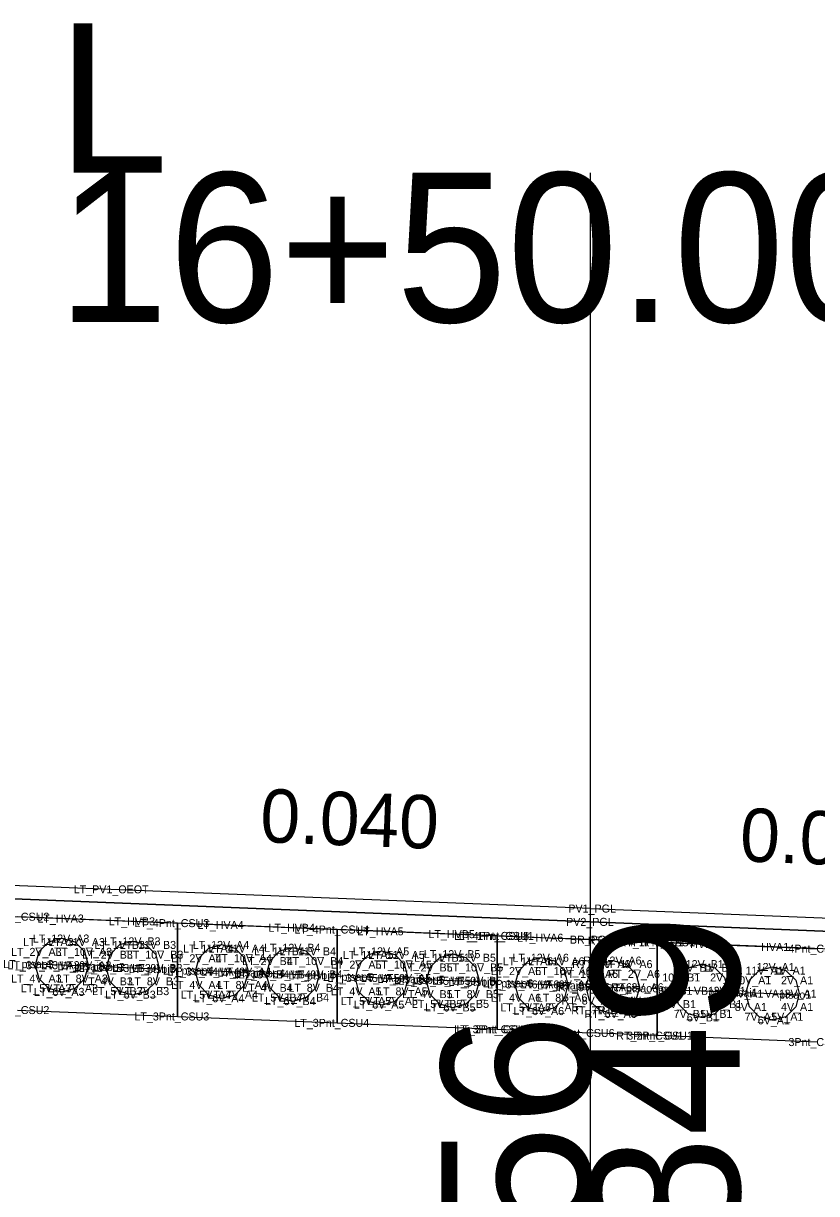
# Model space of a CAD drawing. Extents: x -26 to 1163, y -10 to 9537.
# Drawn here: x 69.36 to 84.24, y 6512.25 to 6534.18 of the extents above; entities that cross this region are included whole.
import ezdxf

# ---------------------------------------------------------------- set-up
doc = ezdxf.new("R2010")
doc.units = 0
for name, color, linetype in [('Exist Cross Section Cell', 7, 'Continuous'), ('Prop CMT Concrete Structures', 7, 'Continuous'), ('Prop CMT Corridor Surface Symbology Blue', 7, 'Continuous'), ('Prop CMT Pvmt Course 1', 7, 'Continuous'), ('Prop CMT Pvmt Course 2', 7, 'Continuous'), ('Prop XS SE Text', 7, 'Continuous'), ('Scratch_Level_0', 7, 'Continuous')]:
    doc.layers.add(name, color=color, linetype=linetype)

msp = doc.modelspace()

# ---------------------------------------------------------------- linework, layer by layer
at = {"layer": 'Exist Cross Section Cell'}
msp.add_line((80, 6500), (80, 6531.385), dxfattribs=at)
at = {"layer": 'Prop CMT Concrete Structures'}
for points in [[(72.25, 6517.317), (71.417, 6517.35), (70.083, 6517.403), (69.25, 6517.437)], [(75.25, 6517.197), (74.417, 6517.23), (73.083, 6517.283), (72.25, 6517.317)], [(72.25, 6517.317), (72.25, 6515.567)], [(72.25, 6515.567), (72.25, 6517.317)], [(78.25, 6517.077), (77.417, 6517.11), (76.083, 6517.163), (75.25, 6517.197)], [(75.25, 6517.197), (75.25, 6515.447)], [(75.25, 6515.447), (75.25, 6517.197)], [(70.083, 6517.028), (69.833, 6516.961), (69.65, 6516.778), (69.583, 6516.528)], [(70.583, 6516.528), (70.516, 6516.778), (70.333, 6516.961), (70.083, 6517.028)], [(71.417, 6516.975), (71.167, 6516.908), (70.984, 6516.725), (70.917, 6516.475)], [(71.917, 6516.475), (71.85, 6516.725), (71.667, 6516.908), (71.417, 6516.975)], [(80, 6517.007), (79.083, 6517.043), (78.25, 6517.077)], [(78.25, 6517.077), (78.25, 6515.327)], [(78.25, 6515.327), (78.25, 6517.077)], [(80, 6515.257), (80, 6517.007)], [(80, 6517.007), (80.417, 6516.99), (81.25, 6516.957)], [(80, 6515.257), (80, 6517.007)], [(81.25, 6516.957), (81.25, 6515.207)], [(81.25, 6516.957), (82.083, 6516.923), (83.417, 6516.87), (84.25, 6516.837)], [(81.25, 6515.207), (81.25, 6516.957)], [(73.083, 6516.908), (72.833, 6516.841), (72.65, 6516.658), (72.583, 6516.408)], [(73.583, 6516.408), (73.516, 6516.658), (73.333, 6516.841), (73.083, 6516.908)], [(74.417, 6516.855), (74.167, 6516.788), (73.984, 6516.605), (73.917, 6516.355)], [(74.917, 6516.355), (74.85, 6516.605), (74.667, 6516.788), (74.417, 6516.855)], [(76.083, 6516.788), (75.833, 6516.721), (75.65, 6516.538), (75.583, 6516.288)], [(76.583, 6516.288), (76.516, 6516.538), (76.333, 6516.721), (76.083, 6516.788)], [(77.417, 6516.735), (77.167, 6516.668), (76.984, 6516.485), (76.917, 6516.235)], [(77.917, 6516.235), (77.85, 6516.485), (77.667, 6516.668), (77.417, 6516.735)], [(69.583, 6516.528), (69.65, 6516.278), (69.833, 6516.095), (70.083, 6516.028), (70.333, 6516.095), (70.516, 6516.278), (70.583, 6516.528)], [(79.083, 6516.668), (78.833, 6516.601), (78.65, 6516.418), (78.583, 6516.168)], [(79.583, 6516.168), (79.516, 6516.418), (79.333, 6516.601), (79.083, 6516.668)], [(79.917, 6516.115), (79.984, 6516.365), (80.167, 6516.548), (80.417, 6516.615)], [(80.417, 6516.615), (80.667, 6516.548), (80.85, 6516.365), (80.917, 6516.115)], [(81.583, 6516.048), (81.65, 6516.298), (81.833, 6516.481), (82.083, 6516.548)], [(82.083, 6516.548), (82.333, 6516.481), (82.516, 6516.298), (82.583, 6516.048)], [(70.917, 6516.475), (70.984, 6516.225), (71.167, 6516.042), (71.417, 6515.975), (71.667, 6516.042), (71.85, 6516.225), (71.917, 6516.475)], [(72.583, 6516.408), (72.65, 6516.158), (72.833, 6515.975), (73.083, 6515.908), (73.333, 6515.975), (73.516, 6516.158), (73.583, 6516.408)], [(73.917, 6516.355), (73.984, 6516.105), (74.167, 6515.922), (74.417, 6515.855), (74.667, 6515.922), (74.85, 6516.105), (74.917, 6516.355)], [(75.583, 6516.288), (75.65, 6516.038), (75.833, 6515.855), (76.083, 6515.788), (76.333, 6515.855), (76.516, 6516.038), (76.583, 6516.288)], [(82.917, 6515.995), (82.984, 6516.245), (83.167, 6516.428), (83.417, 6516.495)], [(83.417, 6516.495), (83.667, 6516.428), (83.85, 6516.245), (83.917, 6515.995)], [(76.917, 6516.235), (76.984, 6515.985), (77.167, 6515.802), (77.417, 6515.735), (77.667, 6515.802), (77.85, 6515.985), (77.917, 6516.235)], [(78.583, 6516.168), (78.65, 6515.918), (78.833, 6515.735), (79.083, 6515.668), (79.333, 6515.735), (79.516, 6515.918), (79.583, 6516.168)], [(80.917, 6516.115), (80.85, 6515.865), (80.667, 6515.682), (80.417, 6515.615), (80.167, 6515.682), (79.984, 6515.865), (79.917, 6516.115)], [(82.583, 6516.048), (82.516, 6515.798), (82.333, 6515.615), (82.083, 6515.548), (81.833, 6515.615), (81.65, 6515.798), (81.583, 6516.048)], [(83.917, 6515.995), (83.85, 6515.745), (83.667, 6515.562), (83.417, 6515.495), (83.167, 6515.562), (82.984, 6515.745), (82.917, 6515.995)], [(69.25, 6515.687), (72.25, 6515.567)], [(72.25, 6515.567), (75.25, 6515.447)], [(75.25, 6515.447), (78.25, 6515.327)], [(78.25, 6515.327), (80, 6515.257)], [(81.25, 6515.207), (80, 6515.257)], [(84.25, 6515.087), (81.25, 6515.207)]]:
    msp.add_lwpolyline(points, dxfattribs=at)
at = {"layer": 'Prop CMT Corridor Surface Symbology Blue'}
for points in [[(70.573, 6516.509), (70.083, 6516.528), (69.593, 6516.548)], [(71.907, 6516.455), (71.417, 6516.475), (70.927, 6516.495)], [(73.573, 6516.389), (73.083, 6516.408), (72.593, 6516.428)], [(74.907, 6516.335), (74.417, 6516.355), (73.927, 6516.375)], [(76.573, 6516.269), (76.083, 6516.288), (75.593, 6516.308)], [(77.907, 6516.215), (77.417, 6516.235), (76.927, 6516.255)], [(79.573, 6516.149), (79.083, 6516.168), (78.593, 6516.188)], [(79.927, 6516.135), (80.417, 6516.115), (80.907, 6516.095)], [(81.593, 6516.068), (82.083, 6516.048), (82.573, 6516.029)], [(82.927, 6516.015), (83.417, 6515.995), (83.907, 6515.975)]]:
    msp.add_lwpolyline(points, dxfattribs=at)
at = {"layer": 'Prop CMT Pvmt Course 1'}
for points in [[(80, 6517.59), (71, 6517.95), (61.5, 6518.33)], [(61.5, 6518.08), (80, 6517.34)], [(80, 6517.34), (80, 6517.59)], [(80, 6517.59), (89, 6517.23), (98.376, 6516.855)], [(80, 6517.34), (80, 6517.59)], [(98.376, 6516.855), (98.376, 6516.605), (80, 6517.34)]]:
    msp.add_lwpolyline(points, dxfattribs=at)
at = {"layer": 'Prop CMT Pvmt Course 2'}
for points in [[(80, 6517.34), (61.5, 6518.08)], [(61.5, 6518.08), (61.5, 6517.747), (80, 6517.007)], [(80, 6517.007), (80, 6517.34)], [(80, 6517.34), (98.376, 6516.605)], [(80, 6517.007), (80, 6517.34)], [(98.376, 6516.605), (98.375, 6516.272), (80, 6517.007)]]:
    msp.add_lwpolyline(points, dxfattribs=at)

# ---------------------------------------------------------------- texts
at = {"layer": 'Exist Cross Section Cell'}
for s, p in [('L', (70, 6531.385)), ('16+50.00 / 1', (70, 6528.585))]:
    msp.add_text(s, height=2.8, dxfattribs=at).set_placement(p)
for s, p in [('E 2058857.4849', (82.8, 6490)), ('N 688729.6356', (80, 6490))]:
    msp.add_text(s, height=2.8, rotation=90, dxfattribs=at).set_placement(p)
at = {"layer": 'Prop XS SE Text'}
for p in [(73.791, 6518.839), (82.791, 6518.479)]:
    msp.add_text('0.040', height=1, rotation=357.7094, dxfattribs=at).set_placement(p)
at = {"layer": 'Scratch_Level_0'}
for s, p in [('LT_PV1_OEOT', (70.306, 6517.875)), ('PV1_PGL', (79.585, 6517.515)), ('LT_4Pnt_CSU2', (68.444, 6517.362)), ('LT_HVA3', (69.625, 6517.328)), ('LT_HVB3', (70.961, 6517.275)), ('LT_4Pnt_CSU3', (71.444, 6517.242)), ('PV2_PGL', (79.543, 6517.265)), ('LT_HVA4', (72.625, 6517.208)), ('LT_HVB4', (73.961, 6517.155)), ('LT_4Pnt_CSU4', (74.444, 6517.122)), ('LT_HVA5', (75.625, 6517.088)), ('LT_HVB5', (76.961, 6517.035)), ('LT_1V_A3', (69.356, 6516.886)), ('LT_12V_A3', (69.539, 6516.953)), ('LT_11V_A3', (69.831, 6516.886)), ('LT_1V_B3', (70.692, 6516.833)), ('LT_12V_B3', (70.875, 6516.9)), ('LT_11V_B3', (71.167, 6516.833)), ('LT_12V_A4', (72.539, 6516.833)), ('LT_4Pnt_CSU5', (77.444, 6517.002)), ('LT_1Pnt_CSU1', (77.53, 6517.002)), ('LT_HVA6', (78.622, 6516.968)), ('BR_PGL', (79.613, 6516.932)), ('RT_HVA6', (79.951, 6516.915)), ('RT_1Pnt_CSU1', (80.526, 6516.882)), ('4Pnt_CSU1', (80.689, 6516.882)), ('HVB1', (81.872, 6516.848)), ('HVA1', (83.203, 6516.795)), ('LT_2V_A3', (69.131, 6516.703)), ('LT_10V_A3', (69.966, 6516.703)), ('LT_2V_B3', (70.466, 6516.65)), ('LT_10V_B3', (71.302, 6516.65)), ('LT_2V_A4', (72.131, 6516.583)), ('LT_1V_A4', (72.356, 6516.766)), ('LT_11V_A4', (72.831, 6516.766)), ('LT_10V_A4', (72.966, 6516.583)), ('LT_1V_B4', (73.692, 6516.713)), ('LT_12V_B4', (73.875, 6516.78)), ('LT_11V_B4', (74.167, 6516.713)), ('LT_1V_A5', (75.356, 6516.646)), ('LT_12V_A5', (75.539, 6516.713)), ('LT_11V_A5', (75.831, 6516.646)), ('LT_1V_B5', (76.692, 6516.593)), ('LT_12V_B5', (76.875, 6516.66)), ('LT_11V_B5', (77.167, 6516.593)), ('LT_12V_A6', (78.535, 6516.593)), ('4Pnt_CSU', (83.714, 6516.762)), ('LT_ptsao3', (68.982, 6516.473)), ('LT_3V_A3', (69.064, 6516.453)), ('LT_VA3', (69.692, 6516.453)), ('LT_ptsai3', (70.002, 6516.434)), ('LT_9V_A3', (70.064, 6516.453)), ('LT_ptsbo3', (70.316, 6516.42)), ('LT_3V_B3', (70.399, 6516.4)), ('LT_VB3', (71.028, 6516.4)), ('LT_ptsbi3', (71.336, 6516.38)), ('LT_9V_B3', (71.399, 6516.4)), ('LT_ptsao4', (71.982, 6516.353)), ('LT_2V_B4', (73.466, 6516.53)), ('LT_10V_B4', (74.302, 6516.53)), ('LT_2V_A5', (75.131, 6516.463)), ('LT_10V_A5', (75.966, 6516.463)), ('LT_2V_B5', (76.466, 6516.41)), ('LT_10V_B5', (77.302, 6516.41)), ('LT_1V_A6', (78.353, 6516.526)), ('LT_11V_A6', (78.828, 6516.526)), ('RT_11V_A6', (79.658, 6516.473)), ('RT_12V_A6', (79.865, 6516.54)), ('RT_1V_A6', (80.182, 6516.473)), ('11V_B1', (81.578, 6516.406)), ('12V_B1', (81.786, 6516.473)), ('1V_B1', (82.103, 6516.406)), ('11V_A1', (82.909, 6516.353)), ('12V_A1', (83.117, 6516.42)), ('1V_A1', (83.434, 6516.353)), ('LT_4V_A3', (69.131, 6516.203)), ('LT_8V_A3', (69.997, 6516.203)), ('LT_4V_B3', (70.466, 6516.15)), ('LT_8V_B3', (71.332, 6516.15)), ('LT_3V_A4', (72.064, 6516.333)), ('LT_VA4', (72.692, 6516.333)), ('LT_ptsai4', (73.002, 6516.314)), ('LT_9V_A4', (73.064, 6516.333)), ('LT_ptsbo4', (73.316, 6516.3)), ('LT_3V_B4', (73.399, 6516.28)), ('LT_VB4', (74.028, 6516.28)), ('LT_ptsbi4', (74.336, 6516.26)), ('LT_9V_B4', (74.399, 6516.28)), ('LT_ptsao5', (74.982, 6516.233)), ('LT_3V_A5', (75.064, 6516.213)), ('LT_VA5', (75.692, 6516.213)), ('LT_ptsai5', (76.002, 6516.194)), ('LT_9V_A5', (76.064, 6516.213)), ('LT_ptsbo5', (76.316, 6516.18)), ('LT_3V_B5', (76.399, 6516.16)), ('LT_VB5', (77.028, 6516.16)), ('LT_ptsbi5', (77.336, 6516.14)), ('LT_9V_B5', (77.399, 6516.16)), ('LT_2V_A6', (78.127, 6516.343)), ('LT_10V_A6', (78.962, 6516.343)), ('RT_10V_A6', (79.426, 6516.29)), ('RT_2V_A6', (80.323, 6516.29)), ('10V_B1', (81.347, 6516.223)), ('2V_B1', (82.244, 6516.223)), ('10V_A1', (82.678, 6516.17)), ('2V_A1', (83.574, 6516.17)), ('LT_5V_A3', (69.314, 6516.02)), ('LT_6V_A3', (69.56, 6515.953)), ('LT_7V_A3', (69.814, 6516.02)), ('LT_5V_B3', (70.649, 6515.967)), ('LT_7V_B3', (71.149, 6515.967)), ('LT_4V_A4', (72.131, 6516.083)), ('LT_8V_A4', (72.997, 6516.083)), ('LT_4V_B4', (73.466, 6516.03)), ('LT_8V_B4', (74.332, 6516.03)), ('LT_4V_A5', (75.131, 6515.963)), ('LT_8V_A5', (75.997, 6515.963)), ('LT_ptsao6', (77.978, 6516.113)), ('LT_3V_A6', (78.06, 6516.093)), ('LT_VA6', (78.689, 6516.093)), ('LT_ptsai6', (78.998, 6516.074)), ('LT_9V_A6', (79.06, 6516.093)), ('RT_ptsai6', (79.348, 6516.06)), ('RT_9V_A6', (79.39, 6516.04)), ('RT_VA6', (80.019, 6516.04)), ('RT_ptsao6', (80.288, 6516.02)), ('RT_3V_A6', (80.39, 6516.04)), ('ptsbi1', (81.267, 6515.993)), ('9V_B1', (81.31, 6515.973)), ('VB1', (81.939, 6515.973)), ('ptsbo1', (82.207, 6515.954)), ('3V_B1', (82.31, 6515.973)), ('ptsai1', (82.6, 6515.94)), ('9V_A1', (82.641, 6515.92)), ('VA1', (83.27, 6515.92)), ('3V_A1', (83.641, 6515.92)), ('LT_6V_B3', (70.896, 6515.9)), ('LT_5V_A4', (72.314, 6515.9)), ('LT_6V_A4', (72.56, 6515.833)), ('LT_7V_A4', (72.814, 6515.9)), ('LT_5V_B4', (73.649, 6515.847)), ('LT_6V_B4', (73.896, 6515.78)), ('LT_7V_B4', (74.149, 6515.847)), ('LT_5V_A5', (75.314, 6515.78)), ('LT_6V_A5', (75.56, 6515.713)), ('LT_7V_A5', (75.814, 6515.78)), ('LT_4V_B5', (76.466, 6515.91)), ('LT_5V_B5', (76.649, 6515.727)), ('LT_7V_B5', (77.149, 6515.727)), ('LT_8V_B5', (77.332, 6515.91)), ('LT_4V_A6', (78.127, 6515.843)), ('LT_8V_A6', (78.993, 6515.843)), ('RT_8V_A6', (79.457, 6515.79)), ('RT_4V_A6', (80.323, 6515.79)), ('8V_B1', (81.377, 6515.723)), ('4V_B1', (82.244, 6515.723)), ('ptsao1', (83.539, 6515.9)), ('LT_3Pnt_CSU2', (68.444, 6515.612)), ('LT_3Pnt_CSU3', (71.444, 6515.492)), ('LT_6V_B5', (76.896, 6515.66)), ('LT_5V_A6', (78.31, 6515.66)), ('LT_6V_A6', (78.557, 6515.593)), ('LT_7V_A6', (78.81, 6515.66)), ('RT_7V_A6', (79.64, 6515.607)), ('RT_6V_A6', (79.886, 6515.54)), ('RT_5V_A6', (80.14, 6515.607)), ('7V_B1', (81.56, 6515.54)), ('6V_B1', (81.807, 6515.473)), ('5V_B1', (82.06, 6515.54)), ('8V_A1', (82.708, 6515.67)), ('7V_A1', (82.891, 6515.487)), ('5V_A1', (83.391, 6515.487)), ('4V_A1', (83.574, 6515.67)), ('LT_3Pnt_CSU4', (74.444, 6515.372)), ('6V_A1', (83.138, 6515.42)), ('LT_3Pnt_CSU5', (77.444, 6515.252)), ('LT_2Pnt_CSU1', (77.487, 6515.252)), ('3Pnt_CSU6', (79.393, 6515.182)), ('RT_2Pnt_CSU1', (80.483, 6515.132)), ('3Pnt_CSU1', (80.689, 6515.132)), ('3Pnt_CSU', (83.714, 6515.012))]:
    msp.add_text(s, height=0.15, dxfattribs=at).set_placement(p)

doc.saveas('drawing.dxf')
